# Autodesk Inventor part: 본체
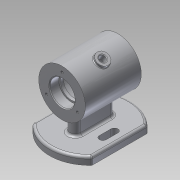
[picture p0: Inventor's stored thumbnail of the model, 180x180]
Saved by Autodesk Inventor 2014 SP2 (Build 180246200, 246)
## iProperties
Created: 2022-02
Part Number: 본체
Material: 알루미늄 6061
Document SubType Name: Modeling
Designer: 거성
Density: 2.71 g/cm^3
Appearance: 알루미늄 - 평지
Author: 거성
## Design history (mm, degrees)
sketch "스케치1"
  geometry: L1 (0, 36)-(0, -36); L2 (16, 36)-(30, 36); L3 (30, 36)-(30, -36); L4 (30, -36)-(16, -36); L5 (16, -36)-(16, -24); L6 (16, -24)-(14, -24); L7 (14, -24)-(14, -20); L8 (14, -20)-(25, -20); L9 (25, -20)-(25, 20); L10 (25, 20)-(14, 20); L11 (14, 20)-(14, 24); L12 (14, 24)-(16, 24); L13 (16, 36)-(16, 24); 2 further points
  constraints: 26 end point, 9 parallel, 3 perpendicular, 2 horizontal alignment, 1 coincident, 1 midpoint, 1 vertical
  dimensions: "d0" = 72 distance of L1.start L1.end; "d1" = 60 diameter of L3 L1; "d2" = 50 diameter of L9 L1; "d3" = 28 diameter of L7 L1; "d4" = 32 diameter of L5 L1; "d5" = 28 diameter of L11 L1; "d6" = 32 diameter of L13 L1; "d7" = 12 distance of L4.end L5.end; "d8" = 12 distance of L2.start L12.end; "d9" = 40 distance of L8.end L9.end; "d10" = 4 distance of L6.end L7.end
revolve "회전1" sketch "스케치1" stored, may be unused: angle "d11" = 90 deg
node "작업 평면1"
sketch "스케치2"
  geometry: L1 (0, 52)-(0, -52); L2 (38, 35.496)-(38, -35.496); L3 (-38, 35.496)-(-38, -35.496); A1 r 52 centre (0, 0) between (38, 35.496) and (38, -35.496); 2 further points
  constraints: 6 end point, 6 point on circle, 2 coincident, 1 centre point, 1 midpoint, 1 vertical
  dimensions: "d13" = 104 diameter of A1; "d17" = 38 distance between parallel lines of L2 L1; "d18" = 38 distance between parallel lines of L3 L1
extrude "돌출1" join sketch "스케치2" distance "d19" = 10; taper "d20" = 0 deg
sketch "스케치3"
  geometry: L1 (-38, 35.496)-(-38, -35.496) reference; L2 (0, -19)-(0, 19); L3 (7, -19)-(7, 19); L4 (-7, 19)-(-7, -19); A1 r 52 centre (0, 0) between (38, 35.496) and (-38, 35.496) reference; A2 r 7 centre (0, -19) between (-7, -19) and (7, -19); A3 r 7 centre (0, 19) between (7, 19) and (-7, 19); 1 further point
  constraints: 8 end point, 4 point on circle, 4 tangent, 2 centre point, 2 parallel, 1 coincident, 1 midpoint
  dimensions: "d21" = 14 diameter of A3; "d22" = 38 distance of L4.start L4.end
extrude "돌출2" join sketch "스케치3" stored distance "d23" = 10; taper "d24" = 0 deg
sketch "스케치4"
  geometry: L1 (-7, -19)-(-7, 19) reference; L2 (-24, -7.5)-(-24, 7.5); L3 (-19.5, -7.5)-(-19.5, 7.5); L4 (-28.5, 7.5)-(-28.5, -7.5); A1 r 52 centre (0, 0) between (38, 35.496) and (-38, 35.496) reference; A2 r 4.5 centre (-24, -7.5) between (-28.5, -7.5) and (-19.5, -7.5); A3 r 4.5 centre (-24, 7.5) between (-19.5, 7.5) and (-28.5, 7.5); 1 further point
  constraints: 8 end point, 4 point on circle, 4 tangent, 2 centre point, 2 parallel, 1 horizontal alignment, 1 midpoint
  dimensions: "d25" = 9 diameter of A3; "d27" = 15 distance of L4.start L4.end; "d28" = 24 distance of A1.centre point (-24, 0)
extrude "돌출3" cut sketch "스케치4" distance "d29" = 10; taper "d30" = 0 deg
fillet "모깎기1" dims "d31" = 3
fillet "모깎기2" dims "d32" = 3
fillet "모깎기3" dims "d33" = 3
fillet "모깎기4" dims "d34" = 0.3
chamfer "모따기1" distance "d35" = 1; stored, may be unused: second distance "d36" = 2, angle "d37" = 45 deg
chamfer "모따기2" distance "d38" = 1; stored, may be unused: second distance "d39" = 2, angle "d40" = 45 deg
sketch "스케치5" dims "d41" = 46
  geometry: L1 (0, 0)-(0, 23); C1 r 17 at (0, 0) reference; 1 further point
  constraints: 2 coincident, 2 end point, 1 vertical, 1 vertical alignment, 2 other
hole "구멍1" sketch "스케치5" at (0, 23) diameter "d42" = 3.242; stored, may be unused: countersink angle "d46" = 90 deg, drill point angle "d48" = 118 deg; dims "d43" = 8, "d44" = 4, "d45" = 2, "d47" = 10
node "작업 평면2"
node "작업 평면3"
node "작업 평면4"
sketch "스케치7"
  geometry: L1 (0, 0)-(0, 32.964); L2 (0, 0)-(28.579, 16.5)
  constraints: 4 end point, 1 vertical
  dimensions: "d63" = 32.96436 distance of L1.start L1.end; "d64" = 33 distance of L1.start L2.end; "d65" = 60 deg angle of L1 L2
node "작업 평면6"
  node "작업 평면5"
node "작업 평면7"
node "작업 평면8"
sketch "스케치9"
  geometry: L1 (0, 0)-(16.5, 28.579); L2 (0, 0)-(33, 0)
  constraints: 4 end point, 1 equal length, 1 horizontal
  dimensions: "d77" = 33 distance of L1.start L1.end; "d78" = 60 deg angle of L2 L1
node "작업 평면9"
sketch "스케치10"
  geometry: C1 r 8 at (0, 0); C2 r 4 at (0, 0); 1 further point
  constraints: 2 centre point, 2 coincident
  dimensions: "d79" = 16 diameter of C1; "d80" = 8 diameter of C2
extrude "돌출6" join sketch "스케치10" stored distance "d81" = 3; taper "d82" = 0 deg
extrude "돌출7" cut sketch "스케치10" stored distance "d83" = 3; taper "d84" = 0 deg
fillet "모깎기5" dims "d85" = 1
fillet "모깎기6" dims "d86" = 1
node "솔리드1"
mirror "대칭1"
pattern_circular "원형 패턴1" dims angle "d50" = 360 deg
mirror "대칭2"
other parameters: "d12" = -62, "d52" = 0, "d53" = 0, "d57" = 0, "d66" = 90 deg, "d73" = 0, "d74" = 0
